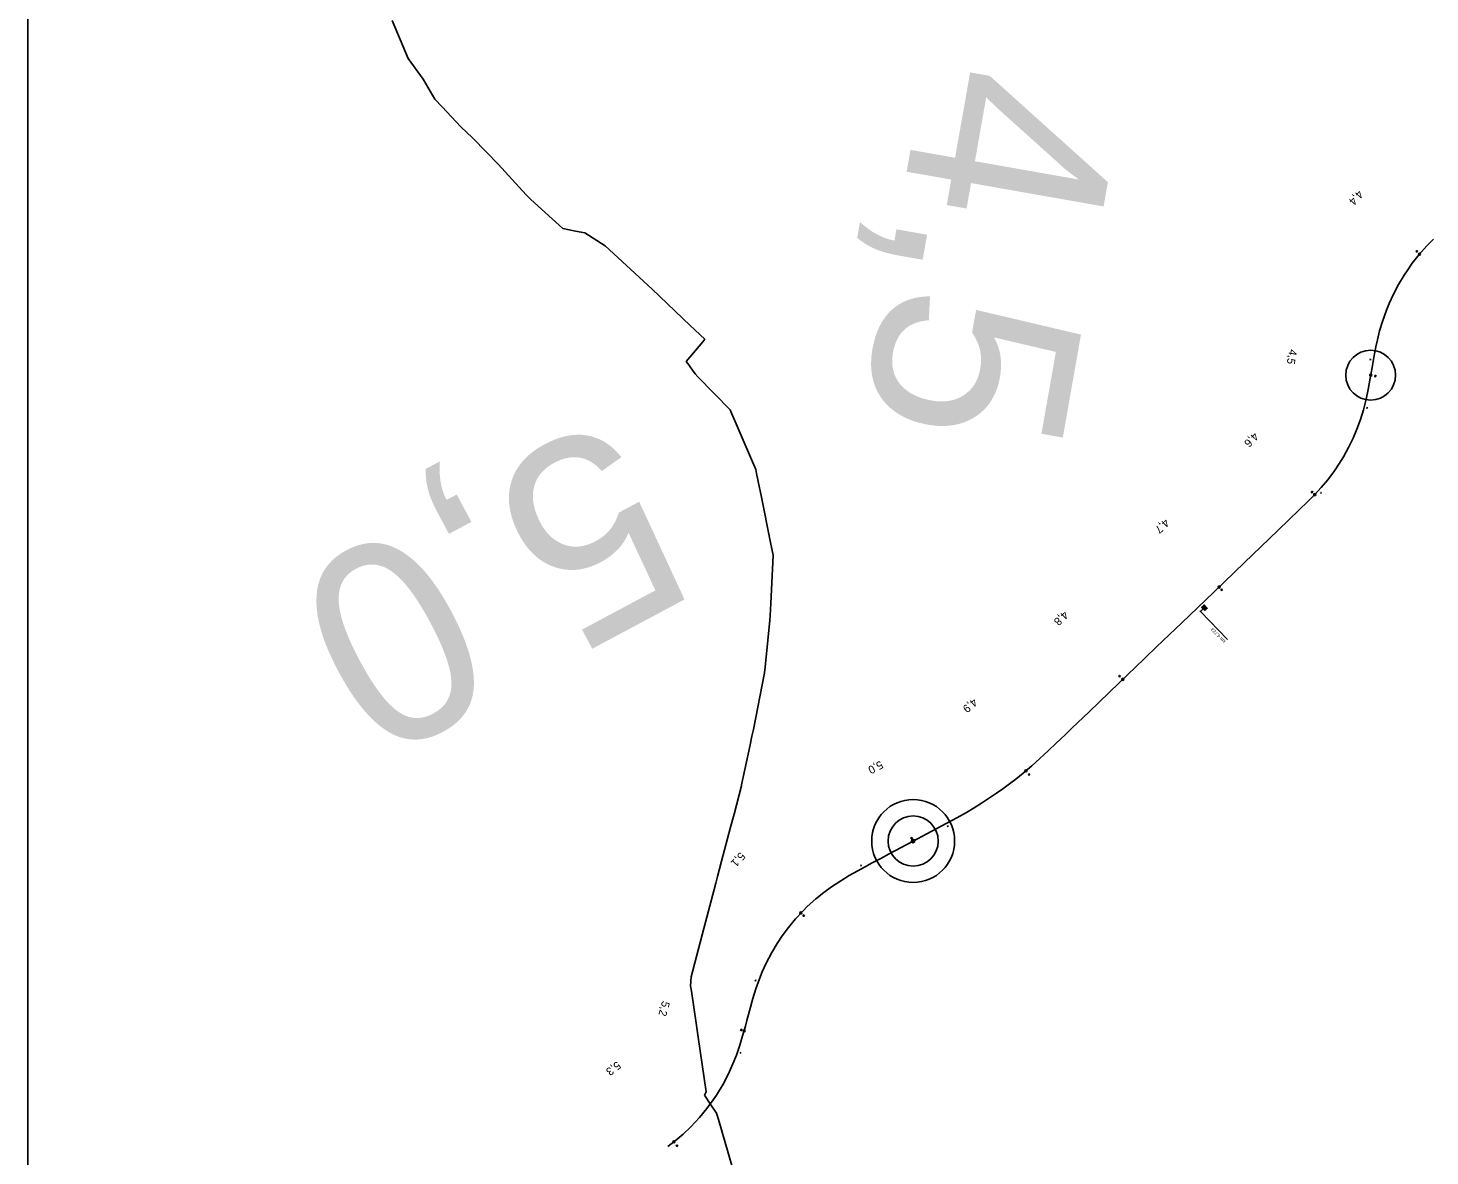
# Model space of a CAD drawing. Extents: x -738519 to -733269, y -1123734 to -1116309.
# Drawn here: x -738519 to -737468, y -1122148 to -1121302 of the extents above; entities that cross this region are included whole.
import ezdxf

# ---------------------------------------------------------------- set-up
doc = ezdxf.new("R2010")
doc.units = 0
for name, color, linetype in [('Implicitní', 7, 'Continuous'), ('Vrstva 1', 7, 'Continuous'), ('Vrstva 13', 7, 'Continuous'), ('Vrstva 7', 7, 'Continuous')]:
    doc.layers.add(name, color=color, linetype=linetype)

msp = doc.modelspace()

# ---------------------------------------------------------------- linework, layer by layer
at = {"layer": 'Implicitní'}
msp.add_line((-738519, -1123733.5), (-738519, -1116308.5), dxfattribs=at)
at = {"layer": 'Vrstva 1'}
for points in [[(-737464.9, -1121460.2), (-737469.9, -1121465.2), (-737475.7, -1121471.8), (-737480.9, -1121478.3), (-737484.3, -1121483.1), (-737487, -1121487.2), (-737491.2, -1121494.2), (-737495.1, -1121501.5), (-737498.2, -1121508.5), (-737500.3, -1121513.4), (-737503.2, -1121521.9), (-737505.4, -1121529), (-737507, -1121535.8), (-737508.2, -1121541.1), (-737509.7, -1121548.9), (-737511.1, -1121556.5), (-737512.5, -1121564.5), (-737514.1, -1121573.1), (-737515.6, -1121580.3), (-737517.6, -1121588.2), (-737519.8, -1121595.6), (-737522.4, -1121602.7), (-737525.3, -1121609.4), (-737528.7, -1121616.5), (-737532.5, -1121623.5), (-737536, -1121629.1), (-737539.3, -1121634.1), (-737544.3, -1121640.7), (-737549.2, -1121646.5), (-737554.1, -1121651.9), (-737559.6, -1121657.5), (-737565.1, -1121662.9), (-737573.9, -1121671.4), (-737588.1, -1121685)], [(-737464.9, -1121460.2), (-737469.9, -1121465.2), (-737475.7, -1121471.8), (-737480.9, -1121478.3), (-737484.3, -1121483.1), (-737487, -1121487.2), (-737491.2, -1121494.2), (-737495.1, -1121501.5), (-737498.2, -1121508.5), (-737500.3, -1121513.4), (-737503.2, -1121521.9), (-737505.4, -1121529), (-737507, -1121535.8), (-737508.2, -1121541.1), (-737509.7, -1121548.9), (-737511.1, -1121556.5), (-737512.5, -1121564.5), (-737514.1, -1121573.1), (-737515.6, -1121580.3), (-737517.6, -1121588.2), (-737519.8, -1121595.6), (-737522.4, -1121602.7), (-737525.3, -1121609.4), (-737528.7, -1121616.5), (-737532.5, -1121623.5), (-737536, -1121629.1), (-737539.3, -1121634.1), (-737544.3, -1121640.7), (-737549.2, -1121646.5), (-737554.1, -1121651.9), (-737559.6, -1121657.5), (-737565.1, -1121662.9), (-737573.9, -1121671.4), (-737588.1, -1121685)], [(-737588.1, -1121685), (-737606.7, -1121702.8), (-737629.8, -1121725), (-737653.8, -1121748.1), (-737672.7, -1121766.2), (-737689.3, -1121782.2)], [(-737588.1, -1121685), (-737606.7, -1121702.8), (-737629.8, -1121725), (-737653.8, -1121748.1), (-737672.7, -1121766.2), (-737689.3, -1121782.2)], [(-737689.3, -1121782.2), (-737693.4, -1121786.1), (-737700.8, -1121793.2), (-737723.2, -1121814.8), (-737736.2, -1121827.2), (-737740.7, -1121831.6), (-737745, -1121835.7), (-737747.9, -1121838.4), (-737753.7, -1121844), (-737760.2, -1121850), (-737766.2, -1121855.4), (-737772.6, -1121860.8), (-737778.2, -1121865.3), (-737781.9, -1121868.2), (-737787.9, -1121872.7), (-737792.6, -1121875.9), (-737797.1, -1121879), (-737803.1, -1121882.9), (-737809.4, -1121886.8), (-737815.3, -1121890.3), (-737822.5, -1121894.3), (-737830, -1121898.3), (-737838, -1121902.6), (-737845, -1121906.3), (-737855.2, -1121911.8), (-737873.1, -1121921.4), (-737879.5, -1121924.8), (-737885.9, -1121928.2), (-737891.6, -1121931.4), (-737896.8, -1121934.2), (-737903.1, -1121937.8), (-737909.5, -1121941.6), (-737916.5, -1121946.2), (-737922.2, -1121950.4), (-737928.3, -1121955.3), (-737934.6, -1121961), (-737937.8, -1121964.2), (-737943.4, -1121970.2), (-737948.8, -1121976.8), (-737953.4, -1121983), (-737957.1, -1121988.6), (-737961.2, -1121995.4), (-737965.4, -1122003.4), (-737968.4, -1122010), (-737970.5, -1122015.3), (-737973.2, -1122022.8), (-737975.4, -1122030.1), (-737978, -1122039.3), (-737979.9, -1122046.4), (-737981, -1122050.7), (-737983.1, -1122058), (-737985.1, -1122064.9), (-737987.7, -1122072.6), (-737990.3, -1122079.1), (-737993.8, -1122086.9), (-737997.7, -1122094.3), (-738002.7, -1122102.5), (-738005.1, -1122106.1), (-738009.9, -1122112.6), (-738015.3, -1122119.2), (-738021.8, -1122126.2), (-738027.6, -1122131.7), (-738033.6, -1122136.8), (-738039.1, -1122141.1)], [(-737689.3, -1121782.2), (-737693.4, -1121786.1), (-737700.8, -1121793.2), (-737723.2, -1121814.8), (-737736.2, -1121827.2), (-737740.7, -1121831.6), (-737745, -1121835.7), (-737747.9, -1121838.4), (-737753.7, -1121844), (-737760.2, -1121850), (-737766.2, -1121855.4), (-737772.6, -1121860.8), (-737778.2, -1121865.3), (-737781.9, -1121868.2), (-737787.9, -1121872.7), (-737792.6, -1121875.9), (-737797.1, -1121879), (-737803.1, -1121882.9), (-737809.4, -1121886.8), (-737815.3, -1121890.3), (-737822.5, -1121894.3), (-737830, -1121898.3), (-737838, -1121902.6), (-737845, -1121906.3), (-737855.2, -1121911.8), (-737873.1, -1121921.4), (-737879.5, -1121924.8), (-737885.9, -1121928.2), (-737891.6, -1121931.4), (-737896.8, -1121934.2), (-737903.1, -1121937.8), (-737909.5, -1121941.6), (-737916.5, -1121946.2), (-737922.2, -1121950.4), (-737928.3, -1121955.3), (-737934.6, -1121961), (-737937.8, -1121964.2), (-737943.4, -1121970.2), (-737948.8, -1121976.8), (-737953.4, -1121983), (-737957.1, -1121988.6), (-737961.2, -1121995.4), (-737965.4, -1122003.4), (-737968.4, -1122010), (-737970.5, -1122015.3), (-737973.2, -1122022.8), (-737975.4, -1122030.1), (-737978, -1122039.3), (-737979.9, -1122046.4), (-737981, -1122050.7), (-737983.1, -1122058), (-737985.1, -1122064.9), (-737987.7, -1122072.6), (-737990.3, -1122079.1), (-737993.8, -1122086.9), (-737997.7, -1122094.3), (-738002.7, -1122102.5), (-738005.1, -1122106.1), (-738009.9, -1122112.6), (-738015.3, -1122119.2), (-738021.8, -1122126.2), (-738027.6, -1122131.7), (-738033.6, -1122136.8), (-738039.1, -1122141.1)]]:
    msp.add_lwpolyline(points, dxfattribs=at)
at = {"layer": 'Vrstva 13'}
for p, q in [((-738245.8, -1121296), (-738233.9, -1121324.5)), ((-738233.9, -1121324.5), (-738222.6, -1121340.2)), ((-738222.6, -1121340.2), (-738213.8, -1121355.1)), ((-738213.8, -1121355.1), (-738208.3, -1121361)), ((-738208.3, -1121361), (-738194.4, -1121375.9)), ((-738194.4, -1121375.9), (-738185.6, -1121384.2)), ((-738185.6, -1121384.2), (-738175.1, -1121395)), ((-738175.1, -1121395), (-738166.3, -1121403.9)), ((-738166.3, -1121403.9), (-738145.3, -1121426.9)), ((-738145.3, -1121426.9), (-738142, -1121430.4)), ((-738142, -1121430.4), (-738118, -1121452.3)), ((-738118, -1121452.3), (-738108.4, -1121454.1)), ((-738101.3, -1121455.5), (-738108.4, -1121454.1)), ((-738101.3, -1121455.5), (-738086.2, -1121465.2)), ((-738050.8, -1121497.6), (-738086.2, -1121465.2)), ((-738050.8, -1121497.6), (-738022.3, -1121524.9)), ((-738022.3, -1121524.9), (-738011.4, -1121535.3)), ((-738012.9, -1121537.1), (-738025.4, -1121551.9)), ((-738011.4, -1121535.3), (-738012.9, -1121537.1)), ((-738025.4, -1121551.9), (-738024.4, -1121553.2)), ((-738024.2, -1121553.6), (-738024.4, -1121553.2)), ((-738024.2, -1121553.6), (-738020.7, -1121558.5)), ((-738020.7, -1121558.5), (-738018.7, -1121561.2)), ((-738018.7, -1121561.2), (-738016.6, -1121563.4)), ((-738016.6, -1121563.4), (-737992.3, -1121588.2)), ((-737992.3, -1121588.2), (-737991.3, -1121590.8)), ((-737991.3, -1121590.8), (-737987.9, -1121598.8)), ((-737987.9, -1121598.8), (-737981.9, -1121612.7)), ((-737981.9, -1121612.7), (-737973.2, -1121633.1)), ((-737973.2, -1121633.1), (-737972.6, -1121636.1)), ((-737972.6, -1121636.1), (-737970.4, -1121646.8)), ((-737970.4, -1121646.8), (-737969.2, -1121652.5)), ((-737969.2, -1121652.5), (-737962.2, -1121687.8)), ((-737962.2, -1121687.8), (-737960.3, -1121697.4)), ((-737960.3, -1121697.4), (-737962, -1121733.5)), ((-737962, -1121733.5), (-737962.5, -1121742.6)), ((-737962.6, -1121746), (-737966.2, -1121781.4)), ((-737962.5, -1121742.6), (-737962.6, -1121746)), ((-737966.2, -1121781.4), (-737966.6, -1121785.7)), ((-737966.6, -1121785.7), (-737975, -1121828.2)), ((-737976.1, -1121833.2), (-737977.7, -1121840.9)), ((-737975, -1121828.2), (-737976.1, -1121833.2)), ((-737977.7, -1121840.9), (-737983.8, -1121869.6)), ((-737989.5, -1121891.6), (-737984, -1121870.4)), ((-737983.8, -1121869.6), (-737984, -1121870.4)), ((-737989.5, -1121891.6), (-737992.1, -1121901.5)), ((-737992.1, -1121901.5), (-737998.8, -1121926.8)), ((-737998.8, -1121926.8), (-738001.8, -1121938.4)), ((-738003.1, -1121943.5), (-738001.8, -1121938.4)), ((-738012.1, -1121977.4), (-738003.1, -1121943.5)), ((-738021.6, -1122013.6), (-738012.1, -1121977.4)), ((-738021.6, -1122013.6), (-738022.1, -1122020.4)), ((-738021.5, -1122024.5), (-738022.1, -1122020.4)), ((-738017.7, -1122050.2), (-738021.5, -1122024.5)), ((-738016.5, -1122059), (-738017.7, -1122050.2)), ((-738010.5, -1122099.9), (-738016.5, -1122059)), ((-738011.7, -1122102.4), (-738010.5, -1122099.9)), ((-738007.3, -1122108.9), (-738011.7, -1122102.4)), ((-738007.3, -1122108.9), (-738002.6, -1122115.9)), ((-738002.6, -1122115.9), (-738001.1, -1122120.8)), ((-738001.1, -1122120.8), (-737991.1, -1122155.2))]:
    msp.add_line(p, q, dxfattribs=at)
at = {"layer": 'Vrstva 7'}
for p, q in [((-737477.5, -1121469.4), (-737477.6, -1121469.5)), ((-737477.5, -1121469.4), (-737477.6, -1121469.5)), ((-737511.8, -1121550.5), (-737512.8, -1121550.3)), ((-737511.8, -1121550.5), (-737512.8, -1121550.3)), ((-737512.2, -1121549.9), (-737512.4, -1121550.9)), ((-737512.2, -1121549.9), (-737512.4, -1121550.9)), ((-737508.6, -1121562.8), (-737508.6, -1121562.9)), ((-737508.6, -1121562.8), (-737508.6, -1121562.9)), ((-737514.3, -1121586.8), (-737515.3, -1121586.6)), ((-737514.3, -1121586.8), (-737515.3, -1121586.6)), ((-737514.7, -1121586.2), (-737514.9, -1121587.2)), ((-737514.7, -1121586.2), (-737514.9, -1121587.2)), ((-737556, -1121650), (-737556, -1121650)), ((-737556, -1121650), (-737556, -1121650)), ((-737549, -1121650.9), (-737549.7, -1121650.2)), ((-737549, -1121650.2), (-737549.7, -1121650.9)), ((-737549, -1121650.9), (-737549.7, -1121650.2)), ((-737549, -1121650.2), (-737549.7, -1121650.9)), ((-737623.7, -1121723.2), (-737623.8, -1121723.3)), ((-737623.7, -1121723.2), (-737623.8, -1121723.3)), ((-737640.3, -1121739.1), (-737639.3, -1121740.2)), ((-737640.3, -1121739.1), (-737639.3, -1121740.2)), ((-737639.8, -1121739.7), (-737619.4, -1121760.6)), ((-737639.8, -1121739.7), (-737619.4, -1121760.6)), ((-737638.5, -1121736.7), (-737636.3, -1121735.3)), ((-737638.5, -1121736.7), (-737636.3, -1121735.3)), ((-737635.6, -1121736), (-737637.8, -1121737.4)), ((-737635.6, -1121736), (-737637.8, -1121737.4)), ((-737637.1, -1121738.1), (-737635, -1121736.7)), ((-737637.1, -1121738.1), (-737635, -1121736.7)), ((-737700.3, -1121788), (-737700.4, -1121788.1)), ((-737700.3, -1121788), (-737700.4, -1121788.1)), ((-737768.2, -1121861.9), (-737768.3, -1121862)), ((-737768.2, -1121861.9), (-737768.3, -1121862)), ((-737856.2, -1121909.7), (-737856.3, -1121909.7)), ((-737856.2, -1121909.7), (-737856.3, -1121909.7)), ((-737828.8, -1121900.5), (-737829.7, -1121901)), ((-737828.8, -1121900.5), (-737829.7, -1121901)), ((-737829, -1121901.2), (-737829.5, -1121900.3)), ((-737829, -1121901.2), (-737829.5, -1121900.3)), ((-737893.9, -1121929.9), (-737894.7, -1121930.4)), ((-737893.9, -1121929.9), (-737894.7, -1121930.4)), ((-737894.1, -1121930.6), (-737894.5, -1121929.7)), ((-737894.1, -1121930.6), (-737894.5, -1121929.7)), ((-737937.3, -1121967.7), (-737937.3, -1121967.8)), ((-737937.3, -1121967.7), (-737937.3, -1121967.8)), ((-737972.9, -1122016.7), (-737973.8, -1122016.3)), ((-737972.9, -1122016.7), (-737973.8, -1122016.3)), ((-737973.2, -1122016), (-737973.5, -1122017)), ((-737973.2, -1122016), (-737973.5, -1122017)), ((-737984.1, -1122053.6), (-737984.2, -1122053.7)), ((-737984.1, -1122053.6), (-737984.2, -1122053.7)), ((-737984.2, -1122070.9), (-737985.1, -1122070.6)), ((-737984.2, -1122070.9), (-737985.1, -1122070.6)), ((-737984.5, -1122070.3), (-737984.8, -1122071.2)), ((-737984.5, -1122070.3), (-737984.8, -1122071.2)), ((-738032.3, -1122140.5), (-738032.4, -1122140.6)), ((-738032.3, -1122140.5), (-738032.4, -1122140.6))]:
    msp.add_line(p, q, dxfattribs=at)
msp.add_lwpolyline([(-737639.8, -1121739.7), (-737637.6, -1121737.6), (-737636.4, -1121738.8), (-737634.6, -1121737.1), (-737637, -1121734.6), (-737638.8, -1121736.3), (-737637.6, -1121737.6)], dxfattribs=at)
msp.add_lwpolyline([(-737639.8, -1121739.7), (-737637.6, -1121737.6), (-737636.4, -1121738.8), (-737634.6, -1121737.1), (-737637, -1121734.6), (-737638.8, -1121736.3), (-737637.6, -1121737.6)], dxfattribs=at)
for centre, radius in [((-737477.5, -1121469.4), 0.5), ((-737477.5, -1121469.4), 0.5), ((-737475.4, -1121471.4), 0.75), ((-737475.4, -1121471.4), 0.75), ((-737512.1, -1121562.2), 18.7), ((-737512.1, -1121562.2), 0.75), ((-737508.6, -1121562.9), 0.5), ((-737508.6, -1121562.9), 0.5), ((-737556, -1121650), 0.5), ((-737556, -1121650), 0.5), ((-737554.1, -1121651.9), 0.75), ((-737554.1, -1121651.9), 0.75), ((-737625.8, -1121721.2), 0.75), ((-737625.8, -1121721.2), 0.75), ((-737623.8, -1121723.3), 0.5), ((-737623.8, -1121723.3), 0.5), ((-737700.4, -1121788.1), 0.5), ((-737700.4, -1121788.1), 0.5), ((-737698, -1121790.5), 0.75), ((-737698, -1121790.5), 0.75), ((-737770.6, -1121859.1), 0.75), ((-737770.6, -1121859.1), 0.75), ((-737768.2, -1121861.9), 0.5), ((-737768.2, -1121861.9), 0.5), ((-737855.2, -1121911.8), 31.1), ((-737855.2, -1121911.8), 18.8), ((-737856.3, -1121909.7), 0.5), ((-737856.3, -1121909.7), 0.5), ((-737855.2, -1121911.8), 1.25), ((-737855.2, -1121911.8), 0.752), ((-737939.4, -1121965.8), 0.75), ((-737939.4, -1121965.8), 0.75), ((-737937.3, -1121967.8), 0.5), ((-737937.3, -1121967.8), 0.5), ((-737984.1, -1122053.6), 0.5), ((-737984.1, -1122053.6), 0.5), ((-737982, -1122054.2), 0.75), ((-737982, -1122054.2), 0.75), ((-738034.6, -1122137.6), 0.75), ((-738034.6, -1122137.6), 0.75), ((-738032.3, -1122140.5), 0.5), ((-738032.3, -1122140.5), 0.5)]:
    msp.add_circle(centre, radius, dxfattribs=at)

# ---------------------------------------------------------------- texts
for s, height, rotation, p in [('4,5', 150, 259.9941, (-737845.1, -1121324.6)), ('4,4', 6, 228.4523, (-737521.5, -1121423)), ('4,4', 6, 228.4523, (-737521.5, -1121423)), ('4,5', 6, 259.9941, (-737573.1, -1121542.5)), ('5,0', 150, 208.1352, (-738082.7, -1121590.4)), ('4,6', 6, 225.5695, (-737599.7, -1121604.7)), ('4,6', 6, 225.5695, (-737599.7, -1121604.7)), ('4,7', 6, 223.8356, (-737666.5, -1121669.6)), ('4,7', 6, 223.8356, (-737666.5, -1121669.6)), ('4,8', 6, 223.8625, (-737742.2, -1121738.7)), ('4,8', 6, 223.8625, (-737742.2, -1121738.7)), ('km 4,723', 2.5, 134.2336, (-737620.6, -1121761.8)), ('km 4,723', 2.5, 134.2336, (-737620.6, -1121761.8)), ('4,9', 6, 220.498, (-737810.1, -1121804.3)), ('4,9', 6, 220.498, (-737810.1, -1121804.3)), ('5,0', 6, 208.1352, (-737879.8, -1121851.3)), ('5,1', 6, 227.1273, (-737984.8, -1121919.7)), ('5,1', 6, 227.1273, (-737984.8, -1121919.7)), ('5,2', 6, 254.4665, (-738043.3, -1122031.5)), ('5,2', 6, 254.4665, (-738043.3, -1122031.5)), ('5,3', 6, 217.696, (-738077.3, -1122076.8)), ('5,3', 6, 217.696, (-738077.3, -1122076.8))]:
    msp.add_text(s, height=height, rotation=rotation, dxfattribs=at).set_placement(p)

doc.saveas('drawing.dxf')
